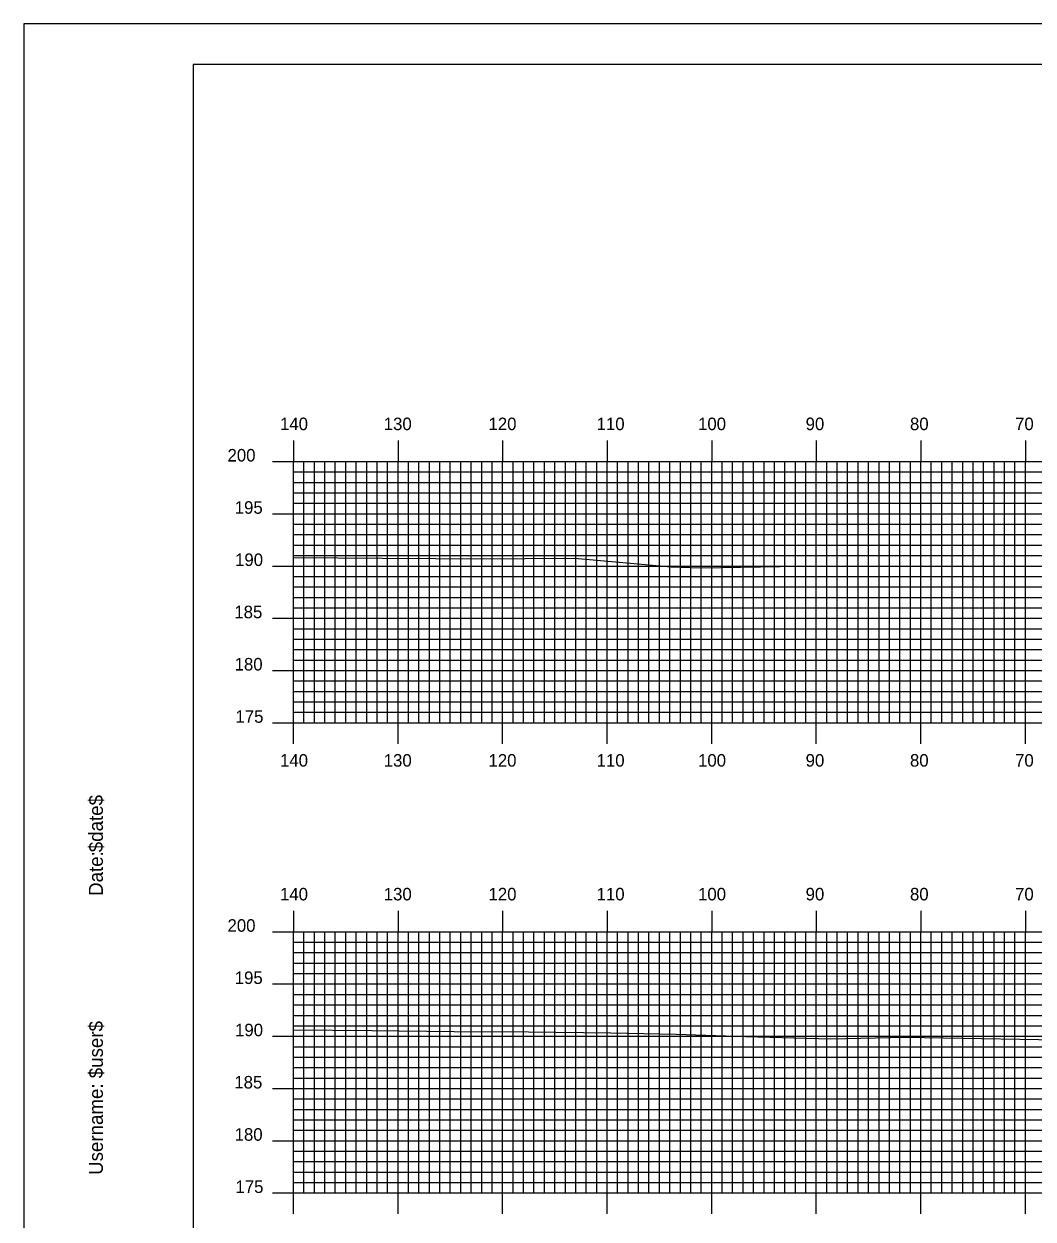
# Model space of a CAD drawing. Extents: x 1797601 to 1797944, y 442591 to 442811.
# Drawn here: x 1797600.7 to 1797697.2, y 442696.2 to 442810.5 of the extents above; entities that cross this region are included whole.
import ezdxf

# ---------------------------------------------------------------- set-up
doc = ezdxf.new("R2010")
doc.units = 0
for name, color, linetype in [('BORDER', 7, 'Continuous'), ('H_V ANNOTATION', 7, 'Continuous'), ('MAJOR', 7, 'Continuous'), ('MINOR', 7, 'Continuous'), ('PLOT BOUNDARY', 7, 'Continuous'), ('S_Roadway_Centerline', 7, 'Continuous')]:
    doc.layers.add(name, color=color, linetype=linetype)

msp = doc.modelspace()

# ---------------------------------------------------------------- linework, layer by layer
at = {"layer": 'BORDER'}
msp.add_lwpolyline([(1797616.84, 442596.67), (1797936.84, 442596.67), (1797936.84, 442806.67), (1797616.84, 442806.67)], close=True, dxfattribs=at)
at = {"layer": 'MAJOR'}
for p, q in [((1797626.44, 442770.67), (1797626.44, 442768.67)), ((1797636.44, 442770.67), (1797636.44, 442768.67)), ((1797646.44, 442770.67), (1797646.44, 442768.67)), ((1797656.44, 442770.67), (1797656.44, 442768.67)), ((1797666.44, 442770.67), (1797666.44, 442768.67)), ((1797676.44, 442770.67), (1797676.44, 442768.67)), ((1797686.44, 442770.67), (1797686.44, 442768.67)), ((1797696.44, 442770.67), (1797696.44, 442768.67)), ((1797624.44, 442768.67), (1797626.44, 442768.67)), ((1797626.44, 442768.67), (1797906.44, 442768.67)), ((1797626.44, 442743.67), (1797626.44, 442768.67)), ((1797626.44, 442743.67), (1797626.44, 442768.67)), ((1797626.44, 442768.67), (1797906.44, 442768.67)), ((1797636.44, 442743.67), (1797636.44, 442768.67)), ((1797646.44, 442743.67), (1797646.44, 442768.67)), ((1797656.44, 442743.67), (1797656.44, 442768.67)), ((1797666.44, 442743.67), (1797666.44, 442768.67)), ((1797676.44, 442743.67), (1797676.44, 442768.67)), ((1797686.44, 442743.67), (1797686.44, 442768.67)), ((1797696.44, 442743.67), (1797696.44, 442768.67)), ((1797624.44, 442763.67), (1797626.44, 442763.67)), ((1797626.44, 442763.67), (1797906.44, 442763.67)), ((1797624.44, 442758.67), (1797626.44, 442758.67)), ((1797626.44, 442758.67), (1797906.44, 442758.67)), ((1797624.44, 442753.67), (1797626.44, 442753.67)), ((1797626.44, 442753.67), (1797906.44, 442753.67)), ((1797624.44, 442748.67), (1797626.44, 442748.67)), ((1797626.44, 442748.67), (1797906.44, 442748.67)), ((1797624.44, 442743.67), (1797626.44, 442743.67)), ((1797626.44, 442743.67), (1797906.44, 442743.67)), ((1797626.44, 442743.67), (1797906.44, 442743.67)), ((1797626.44, 442741.66), (1797626.44, 442743.67)), ((1797636.44, 442741.66), (1797636.44, 442743.67)), ((1797646.44, 442741.66), (1797646.44, 442743.67)), ((1797656.44, 442741.66), (1797656.44, 442743.67)), ((1797666.44, 442741.66), (1797666.44, 442743.67)), ((1797676.44, 442741.66), (1797676.44, 442743.67)), ((1797686.44, 442741.66), (1797686.44, 442743.67)), ((1797696.44, 442741.66), (1797696.44, 442743.67)), ((1797626.44, 442725.67), (1797626.44, 442723.67)), ((1797636.44, 442725.67), (1797636.44, 442723.67)), ((1797646.44, 442725.67), (1797646.44, 442723.67)), ((1797656.44, 442725.67), (1797656.44, 442723.67)), ((1797666.44, 442725.67), (1797666.44, 442723.67)), ((1797676.44, 442725.67), (1797676.44, 442723.67)), ((1797686.44, 442725.67), (1797686.44, 442723.67)), ((1797696.44, 442725.67), (1797696.44, 442723.67)), ((1797624.44, 442723.67), (1797626.44, 442723.67)), ((1797626.44, 442723.67), (1797906.44, 442723.67)), ((1797626.44, 442698.67), (1797626.44, 442723.67)), ((1797626.44, 442698.67), (1797626.44, 442723.67)), ((1797626.44, 442723.67), (1797906.44, 442723.67)), ((1797636.44, 442698.67), (1797636.44, 442723.67)), ((1797646.44, 442698.67), (1797646.44, 442723.67)), ((1797656.44, 442698.67), (1797656.44, 442723.67)), ((1797666.44, 442698.67), (1797666.44, 442723.67)), ((1797676.44, 442698.67), (1797676.44, 442723.67)), ((1797686.44, 442698.67), (1797686.44, 442723.67)), ((1797696.44, 442698.67), (1797696.44, 442723.67)), ((1797624.44, 442718.67), (1797626.44, 442718.67)), ((1797626.44, 442718.67), (1797906.44, 442718.67)), ((1797624.44, 442713.67), (1797626.44, 442713.67)), ((1797626.44, 442713.67), (1797906.44, 442713.67)), ((1797624.44, 442708.67), (1797626.44, 442708.67)), ((1797626.44, 442708.67), (1797906.44, 442708.67)), ((1797624.44, 442703.67), (1797626.44, 442703.67)), ((1797626.44, 442703.67), (1797906.44, 442703.67)), ((1797624.44, 442698.67), (1797626.44, 442698.67)), ((1797626.44, 442698.67), (1797906.44, 442698.67)), ((1797626.44, 442698.67), (1797906.44, 442698.67)), ((1797626.44, 442696.66), (1797626.44, 442698.67)), ((1797636.44, 442696.66), (1797636.44, 442698.67)), ((1797646.44, 442696.66), (1797646.44, 442698.67)), ((1797656.44, 442696.66), (1797656.44, 442698.67)), ((1797666.44, 442696.66), (1797666.44, 442698.67)), ((1797676.44, 442696.66), (1797676.44, 442698.67)), ((1797686.44, 442696.66), (1797686.44, 442698.67)), ((1797696.44, 442696.66), (1797696.44, 442698.67))]:
    msp.add_line(p, q, dxfattribs=at)
at = {"layer": 'MINOR'}
for p, q in [((1797626.44, 442767.67), (1797906.44, 442767.67)), ((1797626.44, 442767.67), (1797628.45, 442767.67)), ((1797627.44, 442743.67), (1797627.44, 442768.67)), ((1797628.44, 442743.67), (1797628.44, 442768.67)), ((1797629.44, 442743.67), (1797629.44, 442768.67)), ((1797630.44, 442743.67), (1797630.44, 442768.67)), ((1797631.44, 442743.67), (1797631.44, 442768.67)), ((1797632.44, 442743.67), (1797632.44, 442768.67)), ((1797633.44, 442743.67), (1797633.44, 442768.67)), ((1797634.44, 442743.67), (1797634.44, 442768.67)), ((1797635.44, 442743.67), (1797635.44, 442768.67)), ((1797637.44, 442743.67), (1797637.44, 442768.67)), ((1797638.44, 442743.67), (1797638.44, 442768.67)), ((1797639.44, 442743.67), (1797639.44, 442768.67)), ((1797640.44, 442743.67), (1797640.44, 442768.67)), ((1797641.44, 442743.67), (1797641.44, 442768.67)), ((1797642.44, 442743.67), (1797642.44, 442768.67)), ((1797643.44, 442743.67), (1797643.44, 442768.67)), ((1797644.44, 442743.67), (1797644.44, 442768.67)), ((1797645.44, 442743.67), (1797645.44, 442768.67)), ((1797647.44, 442743.67), (1797647.44, 442768.67)), ((1797648.44, 442743.67), (1797648.44, 442768.67)), ((1797649.44, 442743.67), (1797649.44, 442768.67)), ((1797650.44, 442743.67), (1797650.44, 442768.67)), ((1797651.44, 442743.67), (1797651.44, 442768.67)), ((1797652.44, 442743.67), (1797652.44, 442768.67)), ((1797653.44, 442743.67), (1797653.44, 442768.67)), ((1797654.44, 442743.67), (1797654.44, 442768.67)), ((1797655.44, 442743.67), (1797655.44, 442768.67)), ((1797657.44, 442743.67), (1797657.44, 442768.67)), ((1797658.44, 442743.67), (1797658.44, 442768.67)), ((1797659.44, 442743.67), (1797659.44, 442768.67)), ((1797660.44, 442743.67), (1797660.44, 442768.67)), ((1797661.44, 442743.67), (1797661.44, 442768.67)), ((1797662.44, 442743.67), (1797662.44, 442768.67)), ((1797663.44, 442743.67), (1797663.44, 442768.67)), ((1797664.44, 442743.67), (1797664.44, 442768.67)), ((1797665.44, 442743.67), (1797665.44, 442768.67)), ((1797667.44, 442743.67), (1797667.44, 442768.67)), ((1797668.44, 442743.67), (1797668.44, 442768.67)), ((1797669.44, 442743.67), (1797669.44, 442768.67)), ((1797670.44, 442743.67), (1797670.44, 442768.67)), ((1797671.44, 442743.67), (1797671.44, 442768.67)), ((1797672.44, 442743.67), (1797672.44, 442768.67)), ((1797673.44, 442743.67), (1797673.44, 442768.67)), ((1797674.44, 442743.67), (1797674.44, 442768.67)), ((1797675.44, 442743.67), (1797675.44, 442768.67)), ((1797677.44, 442743.67), (1797677.44, 442768.67)), ((1797678.44, 442743.67), (1797678.44, 442768.67)), ((1797679.44, 442743.67), (1797679.44, 442768.67)), ((1797680.44, 442743.67), (1797680.44, 442768.67)), ((1797681.44, 442743.67), (1797681.44, 442768.67)), ((1797682.44, 442743.67), (1797682.44, 442768.67)), ((1797683.44, 442743.67), (1797683.44, 442768.67)), ((1797684.44, 442743.67), (1797684.44, 442768.67)), ((1797685.44, 442743.67), (1797685.44, 442768.67)), ((1797687.44, 442743.67), (1797687.44, 442768.67)), ((1797688.44, 442743.67), (1797688.44, 442768.67)), ((1797689.44, 442743.67), (1797689.44, 442768.67)), ((1797690.44, 442743.67), (1797690.44, 442768.67)), ((1797691.44, 442743.67), (1797691.44, 442768.67)), ((1797692.44, 442743.67), (1797692.44, 442768.67)), ((1797693.44, 442743.67), (1797693.44, 442768.67)), ((1797694.44, 442743.67), (1797694.44, 442768.67)), ((1797695.44, 442743.67), (1797695.44, 442768.67)), ((1797626.44, 442766.67), (1797906.44, 442766.67)), ((1797626.44, 442766.67), (1797628.45, 442766.67)), ((1797626.44, 442765.67), (1797906.44, 442765.67)), ((1797626.44, 442765.67), (1797628.45, 442765.67)), ((1797626.44, 442764.67), (1797906.44, 442764.67)), ((1797626.44, 442764.67), (1797628.45, 442764.67)), ((1797626.44, 442762.67), (1797906.44, 442762.67)), ((1797626.44, 442762.67), (1797628.45, 442762.67)), ((1797626.44, 442761.67), (1797906.44, 442761.67)), ((1797626.44, 442761.67), (1797628.45, 442761.67)), ((1797626.44, 442760.67), (1797906.44, 442760.67)), ((1797626.44, 442760.67), (1797628.45, 442760.67)), ((1797626.44, 442759.67), (1797906.44, 442759.67)), ((1797626.44, 442759.67), (1797628.45, 442759.67)), ((1797626.44, 442757.67), (1797906.44, 442757.67)), ((1797626.44, 442757.67), (1797628.45, 442757.67)), ((1797626.44, 442756.67), (1797906.44, 442756.67)), ((1797626.44, 442756.67), (1797628.45, 442756.67)), ((1797626.44, 442755.67), (1797906.44, 442755.67)), ((1797626.44, 442755.67), (1797628.45, 442755.67)), ((1797626.44, 442754.67), (1797906.44, 442754.67)), ((1797626.44, 442754.67), (1797628.45, 442754.67)), ((1797626.44, 442752.67), (1797906.44, 442752.67)), ((1797626.44, 442752.67), (1797628.45, 442752.67)), ((1797626.44, 442751.67), (1797906.44, 442751.67)), ((1797626.44, 442751.67), (1797628.45, 442751.67)), ((1797626.44, 442750.67), (1797906.44, 442750.67)), ((1797626.44, 442750.67), (1797628.45, 442750.67)), ((1797626.44, 442749.67), (1797906.44, 442749.67)), ((1797626.44, 442749.67), (1797628.45, 442749.67)), ((1797626.44, 442747.67), (1797906.44, 442747.67)), ((1797626.44, 442747.67), (1797628.45, 442747.67)), ((1797626.44, 442746.67), (1797906.44, 442746.67)), ((1797626.44, 442746.67), (1797628.45, 442746.67)), ((1797626.44, 442745.67), (1797906.44, 442745.67)), ((1797626.44, 442745.67), (1797628.45, 442745.67)), ((1797626.44, 442744.67), (1797906.44, 442744.67)), ((1797626.44, 442744.67), (1797628.45, 442744.67)), ((1797627.44, 442698.67), (1797627.44, 442723.67)), ((1797628.44, 442698.67), (1797628.44, 442723.67)), ((1797629.44, 442698.67), (1797629.44, 442723.67)), ((1797630.44, 442698.67), (1797630.44, 442723.67)), ((1797631.44, 442698.67), (1797631.44, 442723.67)), ((1797632.44, 442698.67), (1797632.44, 442723.67)), ((1797633.44, 442698.67), (1797633.44, 442723.67)), ((1797634.44, 442698.67), (1797634.44, 442723.67)), ((1797635.44, 442698.67), (1797635.44, 442723.67)), ((1797637.44, 442698.67), (1797637.44, 442723.67)), ((1797638.44, 442698.67), (1797638.44, 442723.67)), ((1797639.44, 442698.67), (1797639.44, 442723.67)), ((1797640.44, 442698.67), (1797640.44, 442723.67)), ((1797641.44, 442698.67), (1797641.44, 442723.67)), ((1797642.44, 442698.67), (1797642.44, 442723.67)), ((1797643.44, 442698.67), (1797643.44, 442723.67)), ((1797644.44, 442698.67), (1797644.44, 442723.67)), ((1797645.44, 442698.67), (1797645.44, 442723.67)), ((1797647.44, 442698.67), (1797647.44, 442723.67)), ((1797648.44, 442698.67), (1797648.44, 442723.67)), ((1797649.44, 442698.67), (1797649.44, 442723.67)), ((1797650.44, 442698.67), (1797650.44, 442723.67)), ((1797651.44, 442698.67), (1797651.44, 442723.67)), ((1797652.44, 442698.67), (1797652.44, 442723.67)), ((1797653.44, 442698.67), (1797653.44, 442723.67)), ((1797654.44, 442698.67), (1797654.44, 442723.67)), ((1797655.44, 442698.67), (1797655.44, 442723.67)), ((1797657.44, 442698.67), (1797657.44, 442723.67)), ((1797658.44, 442698.67), (1797658.44, 442723.67)), ((1797659.44, 442698.67), (1797659.44, 442723.67)), ((1797660.44, 442698.67), (1797660.44, 442723.67)), ((1797661.44, 442698.67), (1797661.44, 442723.67)), ((1797662.44, 442698.67), (1797662.44, 442723.67)), ((1797663.44, 442698.67), (1797663.44, 442723.67)), ((1797664.44, 442698.67), (1797664.44, 442723.67)), ((1797665.44, 442698.67), (1797665.44, 442723.67)), ((1797667.44, 442698.67), (1797667.44, 442723.67)), ((1797668.44, 442698.67), (1797668.44, 442723.67)), ((1797669.44, 442698.67), (1797669.44, 442723.67)), ((1797670.44, 442698.67), (1797670.44, 442723.67)), ((1797671.44, 442698.67), (1797671.44, 442723.67)), ((1797672.44, 442698.67), (1797672.44, 442723.67)), ((1797673.44, 442698.67), (1797673.44, 442723.67)), ((1797674.44, 442698.67), (1797674.44, 442723.67)), ((1797675.44, 442698.67), (1797675.44, 442723.67)), ((1797677.44, 442698.67), (1797677.44, 442723.67)), ((1797678.44, 442698.67), (1797678.44, 442723.67)), ((1797679.44, 442698.67), (1797679.44, 442723.67)), ((1797680.44, 442698.67), (1797680.44, 442723.67)), ((1797681.44, 442698.67), (1797681.44, 442723.67)), ((1797682.44, 442698.67), (1797682.44, 442723.67)), ((1797683.44, 442698.67), (1797683.44, 442723.67)), ((1797684.44, 442698.67), (1797684.44, 442723.67)), ((1797685.44, 442698.67), (1797685.44, 442723.67)), ((1797687.44, 442698.67), (1797687.44, 442723.67)), ((1797688.44, 442698.67), (1797688.44, 442723.67)), ((1797689.44, 442698.67), (1797689.44, 442723.67)), ((1797690.44, 442698.67), (1797690.44, 442723.67)), ((1797691.44, 442698.67), (1797691.44, 442723.67)), ((1797692.44, 442698.67), (1797692.44, 442723.67)), ((1797693.44, 442698.67), (1797693.44, 442723.67)), ((1797694.44, 442698.67), (1797694.44, 442723.67)), ((1797695.44, 442698.67), (1797695.44, 442723.67)), ((1797626.44, 442722.67), (1797906.44, 442722.67)), ((1797626.44, 442722.67), (1797628.45, 442722.67)), ((1797626.44, 442721.67), (1797906.44, 442721.67)), ((1797626.44, 442721.67), (1797628.45, 442721.67)), ((1797626.44, 442720.67), (1797906.44, 442720.67)), ((1797626.44, 442720.67), (1797628.45, 442720.67)), ((1797626.44, 442719.67), (1797906.44, 442719.67)), ((1797626.44, 442719.67), (1797628.45, 442719.67)), ((1797626.44, 442717.67), (1797906.44, 442717.67)), ((1797626.44, 442717.67), (1797628.45, 442717.67)), ((1797626.44, 442716.67), (1797906.44, 442716.67)), ((1797626.44, 442716.67), (1797628.45, 442716.67)), ((1797626.44, 442715.67), (1797906.44, 442715.67)), ((1797626.44, 442715.67), (1797628.45, 442715.67)), ((1797626.44, 442714.67), (1797906.44, 442714.67)), ((1797626.44, 442714.67), (1797628.45, 442714.67)), ((1797626.44, 442712.67), (1797906.44, 442712.67)), ((1797626.44, 442712.67), (1797628.45, 442712.67)), ((1797626.44, 442711.67), (1797906.44, 442711.67)), ((1797626.44, 442711.67), (1797628.45, 442711.67)), ((1797626.44, 442710.67), (1797906.44, 442710.67)), ((1797626.44, 442710.67), (1797628.45, 442710.67)), ((1797626.44, 442709.67), (1797906.44, 442709.67)), ((1797626.44, 442709.67), (1797628.45, 442709.67)), ((1797626.44, 442707.67), (1797906.44, 442707.67)), ((1797626.44, 442707.67), (1797628.45, 442707.67)), ((1797626.44, 442706.67), (1797906.44, 442706.67)), ((1797626.44, 442706.67), (1797628.45, 442706.67)), ((1797626.44, 442705.67), (1797906.44, 442705.67)), ((1797626.44, 442705.67), (1797628.45, 442705.67)), ((1797626.44, 442704.67), (1797906.44, 442704.67)), ((1797626.44, 442704.67), (1797628.45, 442704.67)), ((1797626.44, 442702.67), (1797906.44, 442702.67)), ((1797626.44, 442702.67), (1797628.45, 442702.67)), ((1797626.44, 442701.67), (1797906.44, 442701.67)), ((1797626.44, 442701.67), (1797628.45, 442701.67)), ((1797626.44, 442700.67), (1797906.44, 442700.67)), ((1797626.44, 442700.67), (1797628.45, 442700.67)), ((1797626.44, 442699.67), (1797906.44, 442699.67)), ((1797626.44, 442699.67), (1797628.45, 442699.67))]:
    msp.add_line(p, q, dxfattribs=at)
at = {"layer": 'PLOT BOUNDARY'}
msp.add_lwpolyline([(1797600.66, 442590.55), (1797940.66, 442590.55), (1797940.66, 442810.55), (1797600.66, 442810.55)], close=True, dxfattribs=at)
at = {"layer": 'S_Roadway_Centerline'}
for points in [[(1797626.44, 442759.5), (1797634.95, 442759.41), (1797640.02, 442759.38), (1797643.89, 442759.35), (1797653.32, 442759.42), (1797662.55, 442758.58), (1797665.4, 442758.51), (1797674.89, 442758.65), (1797685.17, 442758.65), (1797687.49, 442758.66), (1797706.84, 442758.62)], [(1797626.44, 442714.29), (1797633.94, 442714.22), (1797641.81, 442714.11), (1797648.92, 442714.08), (1797656.78, 442714.01), (1797663.04, 442713.88), (1797669.67, 442713.65), (1797677.84, 442713.43), (1797684.96, 442713.57), (1797703.19, 442713.25)]]:
    msp.add_lwpolyline(points, dxfattribs=at)

# ---------------------------------------------------------------- texts
at = {"layer": 'BORDER'}
for s, p in [('$date$', (1797608.21, 442731.28)), ('Date:', (1797608.21, 442727.1)), ('$user$', (1797608.21, 442709.65)), ('Username:', (1797608.21, 442700.4))]:
    msp.add_text(s, height=1.339, rotation=90, dxfattribs=at).set_placement(p)
at = {"layer": 'H_V ANNOTATION'}
for s, p in [('140', (1797625.15, 442771.67)), ('130', (1797635.07, 442771.67)), ('120', (1797645.09, 442771.67)), ('110', (1797655.43, 442771.67)), ('100', (1797665.13, 442771.67)), ('90', (1797675.42, 442771.67)), ('80', (1797685.4, 442771.67)), ('70', (1797695.45, 442771.67)), ('200', (1797620.13, 442768.67)), ('195', (1797620.82, 442763.67)), ('190', (1797620.85, 442758.67)), ('185', (1797620.78, 442753.67)), ('180', (1797620.81, 442748.67)), ('175', (1797620.89, 442743.67)), ('140', (1797625.15, 442739.47)), ('130', (1797635.07, 442739.47)), ('120', (1797645.09, 442739.47)), ('110', (1797655.43, 442739.47)), ('100', (1797665.13, 442739.47)), ('90', (1797675.42, 442739.47)), ('80', (1797685.4, 442739.47)), ('70', (1797695.45, 442739.47)), ('140', (1797625.15, 442726.67)), ('130', (1797635.07, 442726.67)), ('120', (1797645.09, 442726.67)), ('110', (1797655.43, 442726.67)), ('100', (1797665.13, 442726.67)), ('90', (1797675.42, 442726.67)), ('80', (1797685.4, 442726.67)), ('70', (1797695.45, 442726.67)), ('200', (1797620.13, 442723.67)), ('195', (1797620.82, 442718.67)), ('190', (1797620.85, 442713.67)), ('185', (1797620.78, 442708.67)), ('180', (1797620.81, 442703.67)), ('175', (1797620.89, 442698.67))]:
    msp.add_text(s, height=1.2, dxfattribs=at).set_placement(p)
at = {"layer": 'MAJOR'}
for p in [(1797626.44, 442743.67), (1797626.44, 442698.67)]:
    msp.add_text('-', height=0.012, dxfattribs=at).set_placement(p)

doc.saveas('drawing.dxf')
